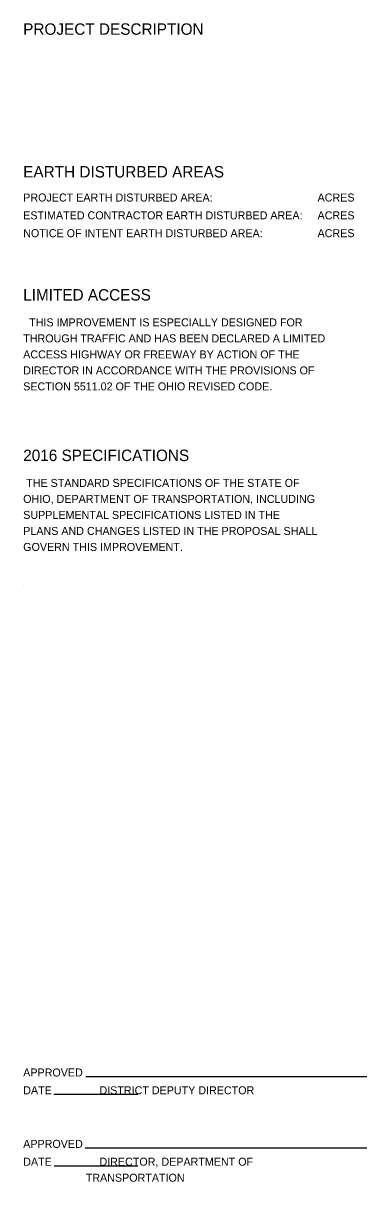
# Model space of a CAD drawing. Extents: x 1862092.2 to 1862141.4, y 420599.8 to 420643.6.
# Drawn here: x 1862122.98 to 1862128.98, y 420623.33 to 420643.6 of the extents above; entities that cross this region are included whole.
import ezdxf

# ---------------------------------------------------------------- set-up
doc = ezdxf.new("R2010")
doc.units = 0
doc.layers.add('SH_Data', color=7, linetype='Continuous')

msp = doc.modelspace()

# ---------------------------------------------------------------- linework, layer by layer
at = {"layer": 'SH_Data'}
for p, q in [((1862122.979, 420633.756), (1862122.979, 420633.756)), ((1862124.074, 420625.176), (1862128.979, 420625.176)), ((1862123.512, 420624.864), (1862124.979, 420624.864)), ((1862124.059, 420623.927), (1862128.979, 420623.927)), ((1862123.521, 420623.615), (1862124.979, 420623.615))]:
    msp.add_line(p, q, dxfattribs=at)

# ---------------------------------------------------------------- texts
for s, height, p in [('PROJECT DESCRIPTION', 0.2, (1862122.979, 420643.396)), ('EARTH DISTURBED AREAS', 0.2, (1862122.979, 420640.9)), ('PROJECT EARTH DISTURBED AREA:', 0.14, (1862122.979, 420640.48)), ('     ACRES', 0.14, (1862127.859, 420640.48)), ('ESTIMATED CONTRACTOR EARTH DISTURBED AREA:', 0.14, (1862122.979, 420640.168)), ('     ACRES', 0.14, (1862127.859, 420640.168)), ('NOTICE OF INTENT EARTH DISTURBED AREA:', 0.14, (1862122.979, 420639.856)), ('     ACRES', 0.14, (1862127.859, 420639.856)), ('LIMITED ACCESS', 0.2, (1862122.979, 420638.748)), ('  THIS IMPROVEMENT IS ESPECIALLY DESIGNED FOR', 0.14, (1862122.979, 420638.296)), ('THROUGH TRAFFIC AND HAS BEEN DECLARED A LIMITED', 0.14, (1862122.979, 420638.016)), ('ACCESS HIGHWAY OR FREEWAY BY ACTION OF THE', 0.14, (1862122.979, 420637.736)), ('DIRECTOR IN ACCORDANCE WITH THE PROVISIONS OF', 0.14, (1862122.979, 420637.456)), ('SECTION 5511.02 OF THE OHIO REVISED CODE.', 0.14, (1862122.979, 420637.176)), ('2016 SPECIFICATIONS', 0.2, (1862122.979, 420635.94)), (' THE STANDARD SPECIFICATIONS OF THE STATE OF', 0.14, (1862122.979, 420635.488)), ('OHIO, DEPARTMENT OF TRANSPORTATION, INCLUDING', 0.14, (1862122.979, 420635.208)), ('SUPPLEMENTAL SPECIFICATIONS LISTED IN THE', 0.14, (1862122.979, 420634.928)), ('PLANS AND CHANGES LISTED IN THE PROPOSAL SHALL', 0.14, (1862122.979, 420634.648)), ('GOVERN THIS IMPROVEMENT.', 0.14, (1862122.979, 420634.368)), ('APPROVED', 0.14, (1862122.979, 420625.176)), ('DATE                DISTRICT DEPUTY DIRECTOR', 0.14, (1862122.979, 420624.864)), ('APPROVED', 0.14, (1862122.979, 420623.927)), ('DATE                DIRECTOR, DEPARTMENT OF', 0.14, (1862122.979, 420623.615)), ('                     TRANSPORTATION', 0.14, (1862122.979, 420623.335))]:
    msp.add_text(s, height=height, dxfattribs=at).set_placement(p)

doc.saveas('drawing.dxf')
